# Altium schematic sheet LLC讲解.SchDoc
size A4; PageSetup: Record=PageOptions|CenterHorizontal=True|CenterVertical=True|PrintScale=1.00|XCorrection=1.00|YCorrection=1.00|PrintKind=2|BorderSize=5000000|LeftOffset=0|BottomOffset=0|Orientation=2|PaperLength=1000|PaperWidth=1000|Scale=100|PaperSource=7|PrintQuality=-4|MediaType=1|DitherType=10|PaperKind=A3|PrintScaleMode=0
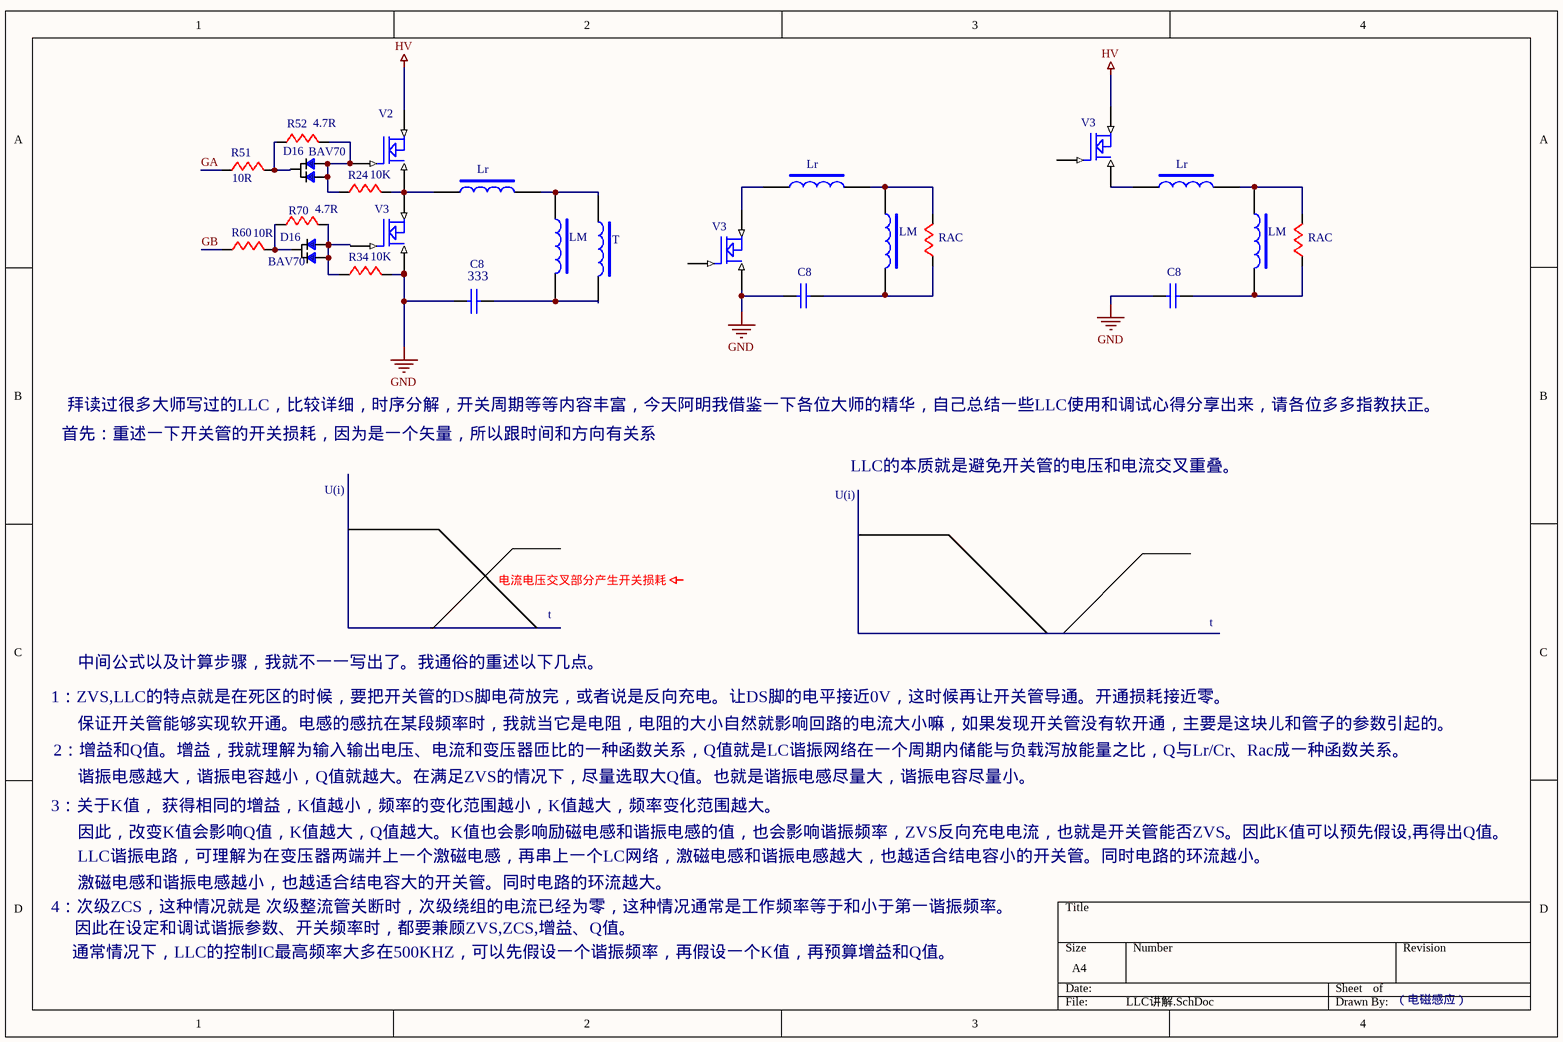
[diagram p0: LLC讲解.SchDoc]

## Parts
(Parts that share a designator on the sheet are numbered #1, #2 ... from top to bottom, then left to right.)
333#1  C8
333#2  C8
333#3  C8
D16#1  BAV70
D16#2  BAV70
LM#1  PQ2625  (value not drawn)
LM#2  PQ2625  (value not drawn)
LM#3  PQ2625  (value not drawn)
Lr#1  PQ2625  (value not drawn)
Lr#2  PQ2625  (value not drawn)
Lr#3  PQ2625  (value not drawn)
R24  10K
R34  10K
R51  10R
R52  4.7R
R60  10R
R70  4.7R
RAC#1  4.7R  (value not drawn)
RAC#2  4.7R  (value not drawn)
T  PQ2625  (value not drawn)
V2  (no value)
V3#1  (no value)
V3#2  (no value)
V3#3  (no value)

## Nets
GND: 333#1.1 333#2.1 333#3.1 R34.2(A) V3#2.3(S) V3#3.3(S)
HV: V2.2(D) V3#1.2(D)
GA: R51.1(A)
GB: R60.1(A)
Net333#1_2: 333#1.2 RAC#1.1(A)
Net333#2_2: 333#2.2 RAC#2.1(A)
Net333#3_2: 333#3.2 LM#3.2 T.2
NetD16#1_1: D16#1.1(A) D16#1.3(A) R24.1(A) R52.2(A) V2.1(G)
NetD16#1_2: D16#1.2(K) R51.2(A) R52.1(A)
NetD16#2_1: D16#2.1(A) D16#2.3(A) R34.1(A) R70.2(A)
NetD16#2_2: D16#2.2(K) R60.2(A) R70.1(A)
NetLM#1_1: LM#1.1 Lr#1.2 RAC#1.2(A)
NetLM#2_1: LM#2.1 Lr#2.2 RAC#2.2(A)
NetLM#3_1: LM#3.1 Lr#3.2 T.1
NetLr#1_1: Lr#1.1 V3#3.2(D)
NetLr#2_1: Lr#2.1 V3#1.3(S)
NetLr#3_1: Lr#3.1 R24.2(A) V2.3(S) V3#2.2(D)

Not connected (* = marked no-connect by the designer): LM#1 2; LM#2 2; V3#1 1(G); V3#2 1(G); V3#3 1(G)

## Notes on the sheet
- 首先：重述一下开关管的开关损耗，因为是一个矢量，所以跟时间和方向有关系
- 拜读过很多大师写过的LLC，比较详细，时序分解，开关周期等等内容丰富，今天阿明我借鉴一下各位大师的精华，自己总结一些LLC使用和调试心得分享出来，请各位多多指教扶正。
- U(i)
- LLC的本质就是避免开关管的电压和电流交叉重叠。
- t
- 1：ZVS,LLC的特点就是在死区的时候，要把开关管的DS脚电荷放完，或者说是反向充电。让DS脚的电平接近0V，这时候再让开关管导通。开通损耗接近零。
- 中间公式以及计算步骤，我就不一一写出了。我通俗的重述以下几点。
- 2：增益和Q值。增益，我就理解为输入输出电压、电流和变压器匝比的一种函数关系，Q值就是LC谐振网络在一个周期内储能与负载泻放能量之比，Q与Lr/Cr、Rac成一种函数关系。
- 保证开关管能够实现软开通。电感的感抗在某段频率时，我就当它是电阻，电阻的大小自然就影响回路的电流大小嘛，如果发现开关管没有软开通，主要是这块儿和管子的参数引起的。
- 谐振电感越大，谐振电容越小，Q值就越大。在满足ZVS的情况下，尽量选取大Q值。也就是谐振电感尽量大，谐振电容尽量小。
- 3：关于K值， 获得相同的增益，K值越小，频率的变化范围越小，K值越大，频率变化范围越大。
- 因此，改变K值会影响Q值，K值越大，Q值越大。K值也会影响励磁电感和谐振电感的值，也会影响谐振频率，ZVS反向充电电流，也就是开关管能否ZVS。因此K值可以预先假设,再得出Q值。
- LLC谐振电路，可理解为在变压器两端并上一个激磁电感，再串上一个LC网络，激磁电感和谐振电感越大，也越适合结电容小的开关管。同时电路的环流越小。
- 4：次级ZCS，这种情况就是 次级整流管关断时，次级绕组的电流已经为零，这种情况通常是工作频率等于和小于第一谐振频率。
- 激磁电感和谐振电感越小，也越适合结电容大的开关管。同时电路的环流越大。
- 通常情况下，LLC的控制IC最高频率大多在500KHZ，可以先假设一个谐振频率，再假设一个K值，再预算增益和Q值。
- 因此在设定和调试谐振参数、开关频率时，都要兼顾ZVS,ZCS,增益、Q值。
- （电磁感应）
- Labels drawn without touching a wire or pin: 电流电压交叉部分产生开关损耗

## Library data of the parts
333#1-333#3 = CAP: Capacitor
D16#1 D16#2 = DIDDE2
LM#1-LM#3 Lr#1-Lr#3 T = INDUCTOR2
R24 R34 R51 R52 R60 R70 RAC#1 RAC#2 = RES
V2 V3#1-V3#3 = MOSFET N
